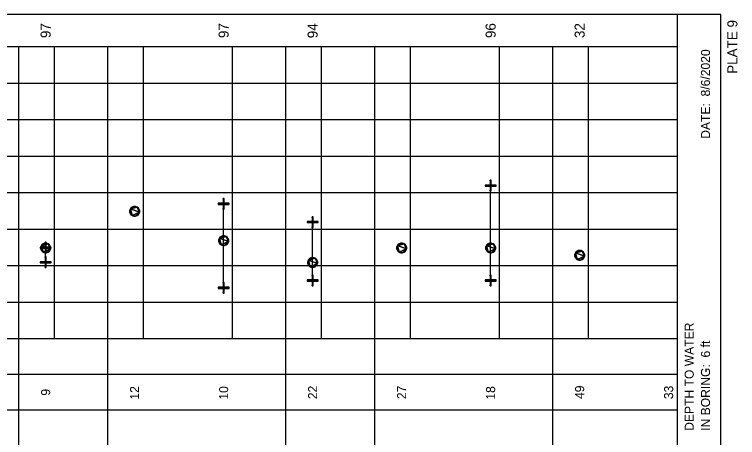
# Model space of a CAD drawing. Extents: x 1313964 to 1316843, y 2087046 to 2096619.
# Drawn here: x 1314195.22 to 1314235.84, y 2089892.52 to 2089916.31 of the extents above; entities that cross this region are included whole.
import ezdxf

# ---------------------------------------------------------------- set-up
doc = ezdxf.new("R2010")
doc.units = 0
doc.layers.add('B-Sub-Contour', color=7, linetype='Continuous')
doc.layers.add('Default', color=7, linetype='Continuous')

# ---------------------------------------------------------------- blocks, each defined once
blk = doc.blocks.new('POINT_DISPLAY')
at = {"layer": 'Default'}
blk.add_line((0, 0), (0, 0), dxfattribs=at)
blk = doc.blocks.new('DMK_101')
at = {"layer": 'Default'}
for points in [[(-14269.212, 2386.584), (-14476.476, 0), (-14269.212, -2386.584), (-14269.212, 2386.584)], [(-12638.532, 6858), (-13653.516, 4690.872), (-14269.212, 2386.584), (-12638.532, 6858)], [(-12638.532, 6858), (-14269.212, 2386.584), (-14269.212, -2386.584), (-12638.532, 6858)], [(-12638.532, 6858), (-14269.212, -2386.584), (-3147.06, -13508.736), (-12638.532, 6858)], [(-3147.06, 13511.784), (-7618.476, 11878.056), (-12638.532, 6858), (-3147.06, 13511.784)], [(6097.524, 11878.056), (-3147.06, 13511.784), (-12638.532, 6858), (6097.524, 11878.056)], [(-7618.476, 11878.056), (-11266.932, 8820.912), (-12638.532, 6858), (-7618.476, 11878.056)], [(-3147.06, -13508.736), (6097.524, 11878.056), (-12638.532, 6858), (-3147.06, -13508.736)], [(-7618.476, 11878.056), (-9578.34, 10506.456), (-11266.932, 8820.912), (-7618.476, 11878.056)], [(-9578.34, 10506.456), (-10456.164, 9698.736), (-11266.932, 8820.912), (-9578.34, 10506.456)], [(-3147.06, 13511.784), (-5451.348, 12893.04), (-7618.476, 11878.056), (-3147.06, 13511.784)], [(1626.108, 13511.784), (-760.476, 13712.952), (-3147.06, 13511.784), (1626.108, 13511.784)], [(6097.524, 11878.056), (1626.108, 13511.784), (-3147.06, 13511.784), (6097.524, 11878.056)], [(-3147.06, -13508.736), (11117.58, -6858), (6097.524, 11878.056), (-3147.06, -13508.736)], [(6097.524, 11878.056), (3930.396, 12893.04), (1626.108, 13511.784), (6097.524, 11878.056)], [(11117.58, 6858), (8060.436, 10506.456), (6097.524, 11878.056), (11117.58, 6858)], [(12751.308, 2386.584), (11117.58, 6858), (6097.524, 11878.056), (12751.308, 2386.584)], [(11117.58, -6858), (12751.308, 2386.584), (6097.524, 11878.056), (11117.58, -6858)], [(9745.98, 8820.912), (8938.26, 9698.736), (8060.436, 10506.456), (9745.98, 8820.912)], [(11117.58, 6858), (9745.98, 8820.912), (8060.436, 10506.456), (11117.58, 6858)], [(12751.308, 2386.584), (12132.564, 4690.872), (11117.58, 6858), (12751.308, 2386.584)], [(11117.58, -6858), (12751.308, -2386.584), (12751.308, 2386.584), (11117.58, -6858)], [(12751.308, -2386.584), (12952.476, 0), (12751.308, 2386.584), (12751.308, -2386.584)], [(-14269.212, -2386.584), (-13653.516, -4690.872), (-12638.532, -6858), (-14269.212, -2386.584)], [(-14269.212, -2386.584), (-12638.532, -6858), (-9578.34, -10506.456), (-14269.212, -2386.584)], [(-14269.212, -2386.584), (-9578.34, -10506.456), (-3147.06, -13508.736), (-14269.212, -2386.584)], [(-12638.532, -6858), (-11266.932, -8817.864), (-9578.34, -10506.456), (-12638.532, -6858)], [(-11266.932, -8817.864), (-10456.164, -9695.688), (-9578.34, -10506.456), (-11266.932, -8817.864)], [(-9578.34, -10506.456), (-7618.476, -11878.056), (-3147.06, -13508.736), (-9578.34, -10506.456)], [(-7618.476, -11878.056), (-5451.348, -12893.04), (-3147.06, -13508.736), (-7618.476, -11878.056)], [(-3147.06, -13508.736), (6097.524, -11878.056), (11117.58, -6858), (-3147.06, -13508.736)], [(-3147.06, -13508.736), (1626.108, -13508.736), (6097.524, -11878.056), (-3147.06, -13508.736)], [(-3147.06, -13508.736), (-760.476, -13716), (1626.108, -13508.736), (-3147.06, -13508.736)], [(1626.108, -13508.736), (3930.396, -12893.04), (6097.524, -11878.056), (1626.108, -13508.736)], [(6097.524, -11878.056), (8060.436, -10506.456), (11117.58, -6858), (6097.524, -11878.056)], [(8060.436, -10506.456), (9745.98, -8817.864), (11117.58, -6858), (8060.436, -10506.456)], [(8060.436, -10506.456), (8938.26, -9695.688), (9745.98, -8817.864), (8060.436, -10506.456)], [(11117.58, -6858), (12132.564, -4690.872), (12751.308, -2386.584), (11117.58, -6858)]]:
    blk.add_lwpolyline(points, close=True, dxfattribs=at)
blk.add_blockref('POINT_DISPLAY', (14479.524, 0), dxfattribs=at)
blk = doc.blocks.new('DMK_99')
at = {"layer": 'Default'}
for points in [[(-1524, -1524), (-1524, 1524), (-15240, 1524), (-1524, -1524)], [(-1524, -1524), (-15240, 1524), (-15240, -1524), (-1524, -1524)], [(1524, 1524), (1524, 15240), (-1524, 15240), (1524, 1524)], [(1524, 1524), (-1524, 15240), (-1524, 1524), (1524, 1524)], [(-1524, -1524), (1524, -1524), (1524, 1524), (-1524, -1524)], [(-1524, -1524), (1524, 1524), (-1524, 1524), (-1524, -1524)], [(1524, -1524), (15240, -1524), (15240, 1524), (1524, -1524)], [(1524, -1524), (15240, 1524), (1524, 1524), (1524, -1524)], [(-1524, -1524), (-1524, -15240), (1524, -15240), (-1524, -1524)], [(-1524, -1524), (1524, -15240), (1524, -1524), (-1524, -1524)]]:
    blk.add_lwpolyline(points, close=True, dxfattribs=at)

msp = doc.modelspace()

# ---------------------------------------------------------------- linework, layer by layer
at = {"layer": 'B-Sub-Contour'}
for points in [[(1314234.904, 2089873.434), (1314234.904, 2089916.306), (1314173.485, 2089916.306), (1314173.485, 2089873.434), (1314234.904, 2089873.434)], [(1314232.471, 2089873.434), (1314232.471, 2089916.306)], [(1314232.471, 2089914.481), (1314180.782, 2089914.481)], [(1314232.471, 2089914.481), (1314187.471, 2089914.481)], [(1314195.471, 2089894.049), (1314195.471, 2089914.481)], [(1314197.471, 2089898.063), (1314197.471, 2089914.481)], [(1314200.471, 2089894.049), (1314200.471, 2089914.481)], [(1314202.471, 2089898.063), (1314202.471, 2089914.481)], [(1314207.471, 2089898.063), (1314207.471, 2089914.481)], [(1314210.471, 2089894.049), (1314210.471, 2089914.481)], [(1314212.471, 2089898.063), (1314212.471, 2089914.481)], [(1314215.471, 2089894.049), (1314215.471, 2089914.481)], [(1314217.471, 2089898.063), (1314217.471, 2089914.481)], [(1314222.471, 2089898.063), (1314222.471, 2089914.481)], [(1314225.471, 2089894.049), (1314225.471, 2089914.481)], [(1314227.471, 2089898.063), (1314227.471, 2089914.481)], [(1314232.471, 2089898.063), (1314232.471, 2089914.481)], [(1314232.471, 2089912.429), (1314187.471, 2089912.429)], [(1314232.471, 2089910.377), (1314187.471, 2089910.377)], [(1314232.471, 2089908.324), (1314187.471, 2089908.324)], [(1314221.971, 2089901.346), (1314221.971, 2089906.683)], [(1314221.971, 2089901.346), (1314221.971, 2089906.683)], [(1314232.471, 2089906.272), (1314187.471, 2089906.272)], [(1314206.971, 2089900.936), (1314206.971, 2089905.656)], [(1314206.971, 2089900.936), (1314206.971, 2089905.656)], [(1314211.971, 2089901.346), (1314211.971, 2089904.63)], [(1314211.971, 2089901.346), (1314211.971, 2089904.63)], [(1314232.471, 2089904.22), (1314187.471, 2089904.22)], [(1314196.971, 2089902.373), (1314196.971, 2089903.194)], [(1314196.971, 2089902.373), (1314196.971, 2089903.194)], [(1314232.471, 2089902.167), (1314187.471, 2089902.167)], [(1314232.471, 2089900.115), (1314187.471, 2089900.115)], [(1314232.471, 2089898.063), (1314180.782, 2089898.063)], [(1314232.471, 2089898.063), (1314187.471, 2089898.063)], [(1314232.471, 2089896.056), (1314180.782, 2089896.056)], [(1314232.471, 2089894.049), (1314180.782, 2089894.049)], [(1314195.471, 2089878.178), (1314195.471, 2089894.049)], [(1314200.471, 2089878.178), (1314200.471, 2089894.049)], [(1314210.471, 2089878.178), (1314210.471, 2089894.049)], [(1314215.471, 2089878.178), (1314215.471, 2089894.049)], [(1314225.471, 2089878.178), (1314225.471, 2089894.049)]]:
    msp.add_lwpolyline(points, dxfattribs=at)

# ---------------------------------------------------------------- block references
at = {"layer": 'B-Sub-Contour', "xscale": 1.9951013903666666e-05, "yscale": 1.9951013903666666e-05, "rotation": 90}
for name, p in [('DMK_99', (1314221.971, 2089906.683)), ('DMK_99', (1314221.971, 2089906.683)), ('DMK_99', (1314206.971, 2089905.656)), ('DMK_99', (1314206.971, 2089905.656)), ('DMK_101', (1314201.971, 2089905.246)), ('DMK_101', (1314201.971, 2089905.246)), ('DMK_99', (1314211.971, 2089904.63)), ('DMK_99', (1314211.971, 2089904.63)), ('DMK_101', (1314206.971, 2089903.604)), ('DMK_101', (1314206.971, 2089903.604)), ('DMK_99', (1314196.971, 2089903.194)), ('DMK_99', (1314196.971, 2089903.194)), ('DMK_101', (1314196.971, 2089903.194)), ('DMK_101', (1314196.971, 2089903.194)), ('DMK_101', (1314216.971, 2089903.194)), ('DMK_101', (1314216.971, 2089903.194)), ('DMK_101', (1314221.971, 2089903.194)), ('DMK_101', (1314221.971, 2089903.194)), ('DMK_101', (1314226.971, 2089902.783)), ('DMK_101', (1314226.971, 2089902.783)), ('DMK_99', (1314196.971, 2089902.373)), ('DMK_99', (1314196.971, 2089902.373)), ('DMK_101', (1314211.971, 2089902.373)), ('DMK_101', (1314211.971, 2089902.373)), ('DMK_99', (1314211.971, 2089901.346)), ('DMK_99', (1314211.971, 2089901.346)), ('DMK_99', (1314221.971, 2089901.346)), ('DMK_99', (1314221.971, 2089901.346)), ('DMK_99', (1314206.971, 2089900.936)), ('DMK_99', (1314206.971, 2089900.936))]:
    msp.add_blockref(name, p, dxfattribs=at)

# ---------------------------------------------------------------- texts
at = {"layer": 'B-Sub-Contour'}
for s, height, p in [('PLATE 9', 0.5655, (1314235.834, 2089912.967)), ('97', 0.5655, (1314197.254, 2089914.977)), ('97', 0.5655, (1314207.254, 2089914.977)), ('94', 0.5655, (1314212.254, 2089914.966)), ('96', 0.5655, (1314222.254, 2089914.977)), ('32', 0.5655, (1314227.254, 2089914.977)), ('DATE:  8/6/2020', 0.50899, (1314234.296, 2089909.313)), ('DEPTH TO WATER', 0.50899, (1314233.383, 2089892.894)), ('IN BORING:  6 ft', 0.50899, (1314234.296, 2089892.894)), ('9', 0.509, (1314197.226, 2089894.873)), ('12', 0.509, (1314202.226, 2089894.646)), ('10', 0.509, (1314207.226, 2089894.646)), ('22', 0.509, (1314212.226, 2089894.674)), ('27', 0.509, (1314217.226, 2089894.674)), ('18', 0.509, (1314222.226, 2089894.646)), ('49', 0.509, (1314227.226, 2089894.684)), ('33', 0.509, (1314232.226, 2089894.674))]:
    msp.add_text(s, height=height, rotation=90, dxfattribs=at).set_placement(p)

doc.saveas('drawing.dxf')
